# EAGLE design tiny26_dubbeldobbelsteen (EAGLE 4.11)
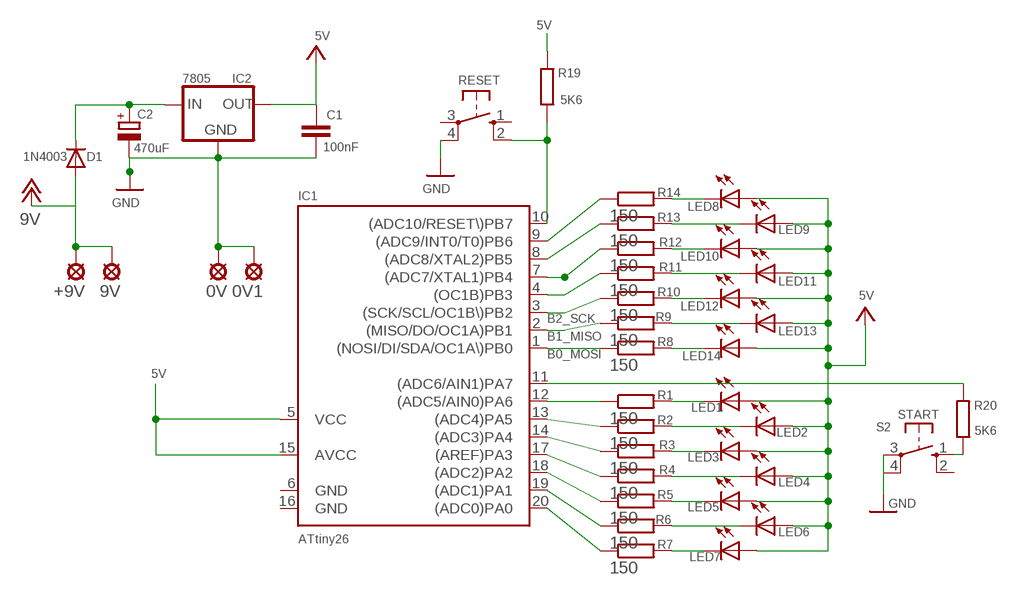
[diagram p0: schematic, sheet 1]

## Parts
0V  SE14  [SE14]
0V1  SE14  [SE14]
9V  SE14  [SE14]
+9V  SE14  [SE14]
C1  100nF  C-EU050-025X075  [C050-025X075]
C2  470uF  CPOL-EUE5-6  [E5-6]
D1  1N4003  DIODE-D-12.5  [D-12.5]
IC1  ATtiny26  TINY26LP  [DIL20]
IC2  7805  78XXS  [78XXS]
LED1  LED3MM  [LED3MM]
LED2  LED3MM  [LED3MM]
LED3  LED3MM  [LED3MM]
LED4  LED3MM  [LED3MM]
LED5  LED3MM  [LED3MM]
LED6  LED3MM  [LED3MM]
LED7  LED3MM  [LED3MM]
LED8  LED3MM  [LED3MM]
LED9  LED3MM  [LED3MM]
LED10  LED3MM  [LED3MM]
LED11  LED3MM  [LED3MM]
LED12  LED3MM  [LED3MM]
LED13  LED3MM  [LED3MM]
LED14  LED3MM  [LED3MM]
R1  150  R-EU_0207/10  [0207/10]
R2  150  R-EU_0207/10  [0207/10]
R3  150  R-EU_0207/10  [0207/10]
R4  150  R-EU_0207/10  [0207/10]
R5  150  R-EU_0207/10  [0207/10]
R6  150  R-EU_0207/10  [0207/10]
R7  150  R-EU_0207/10  [0207/10]
R8  150  R-EU_0207/10  [0207/10]
R9  150  R-EU_0207/10  [0207/10]
R10  150  R-EU_0207/10  [0207/10]
R11  150  R-EU_0207/10  [0207/10]
R12  150  R-EU_0207/10  [0207/10]
R13  150  R-EU_0207/10  [0207/10]
R14  150  R-EU_0207/10  [0207/10]
R19  5K6  R-EU_0207/10  [0207/10]
R20  5K6  R-EU_0207/10  [0207/10]
RESET  10-XX  [B3F-10XX]
S2  START  10-XX  [B3F-10XX]

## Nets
5V: C1.1 IC1.5(VCC) IC1.15(AVCC) IC2.OUT LED1.A LED2.A LED3.A LED4.A LED5.A LED6.A LED7.A LED8.A LED9.A LED10.A LED11.A LED12.A LED13.A LED14.A R19.2
+9V: 9V.MP +9V.MP D1.A ; supply symbol labelled 9V
B0_MOSI: IC1.1((NOSI/DI/SDA/OC1A\)PB0) R8.1
B1_MISO: IC1.2((MISO/DO/OC1A)PB1) R9.1
B2_SCK: IC1.3((SCK/SCL/OC1B\)PB2) R10.1
B3: IC1.4((OC1B)PB3) R11.1
B4: IC1.7((ADC7/XTAL1)PB4) R12.1
GND: 0V1.MP 0V.MP C1.2 C2.- IC2.GND RESET.4(P1) S2.3(P)
N$3: R20.1 S2.1(S)
N$5: LED7.K(C) R7.2
N$6: LED6.K(C) R6.2
N$7: LED5.K(C) R5.2
N$8: LED4.K(C) R4.2
N$9: LED3.K(C) R3.2
N$10: C2.+ D1.C IC2.IN
N$11: LED2.K(C) R2.2
N$12: LED1.K(C) R1.2
N$14: IC1.20((ADC0)PA0) R7.1
N$15: IC1.19((ADC1)PA1) R6.1
N$17: IC1.18((ADC2)PA2) R5.1
N$18: IC1.17((AREF)PA3) R4.1
N$19: IC1.14((ADC3)PA4) R3.1
N$20: IC1.13((ADC4)PA5) R2.1
N$21: IC1.12((ADC5/AIN0)PA6) R1.1
N$23: LED14.K(C) R8.2
N$24: LED13.K(C) R9.2
N$25: LED12.K(C) R10.2
N$26: LED11.K(C) R11.2
N$27: LED10.K(C) R12.2
N$28: LED9.K(C) R13.2
N$29: LED8.K(C) R14.2
N$30: IC1.8((ADC8/XTAL2)PB5) R13.1
N$31: IC1.9((ADC9/INT0/T0)PB6) R14.1
N$62: IC1.11((ADC6/AIN1)PA7) R20.2
RESET: IC1.10((ADC10/RESET\)PB7) R19.1 RESET.2(S1)
Unconnected: RESET.1(S) RESET.3(P) S2.2(S1) S2.4(P1)

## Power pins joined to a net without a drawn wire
GND: IC1.6(GND) IC1.16(GND)

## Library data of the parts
0V 0V1 9V +9V = solpad:SE14: SOLDER PAD
C1 = rcl:C-EU: CAPACITOR, European symbol
C2 = rcl:CPOL-EU: POLARIZED CAPACITOR, European symbol
D1 = diode:DIODE-: DIODE
IC1 = atmel:TINY26*: 8-bit AVR Microcontroller with 2K Bytes Flash
IC2 = v-reg:78XXS: VOLTAGE REGULATOR
LED1-LED14 = led:LED: LED
R1-R14 R19 R20 = rcl:R-EU_: RESISTOR, European symbol
RESET S2 = switch-omron:10-XX: OMRON SWITCH

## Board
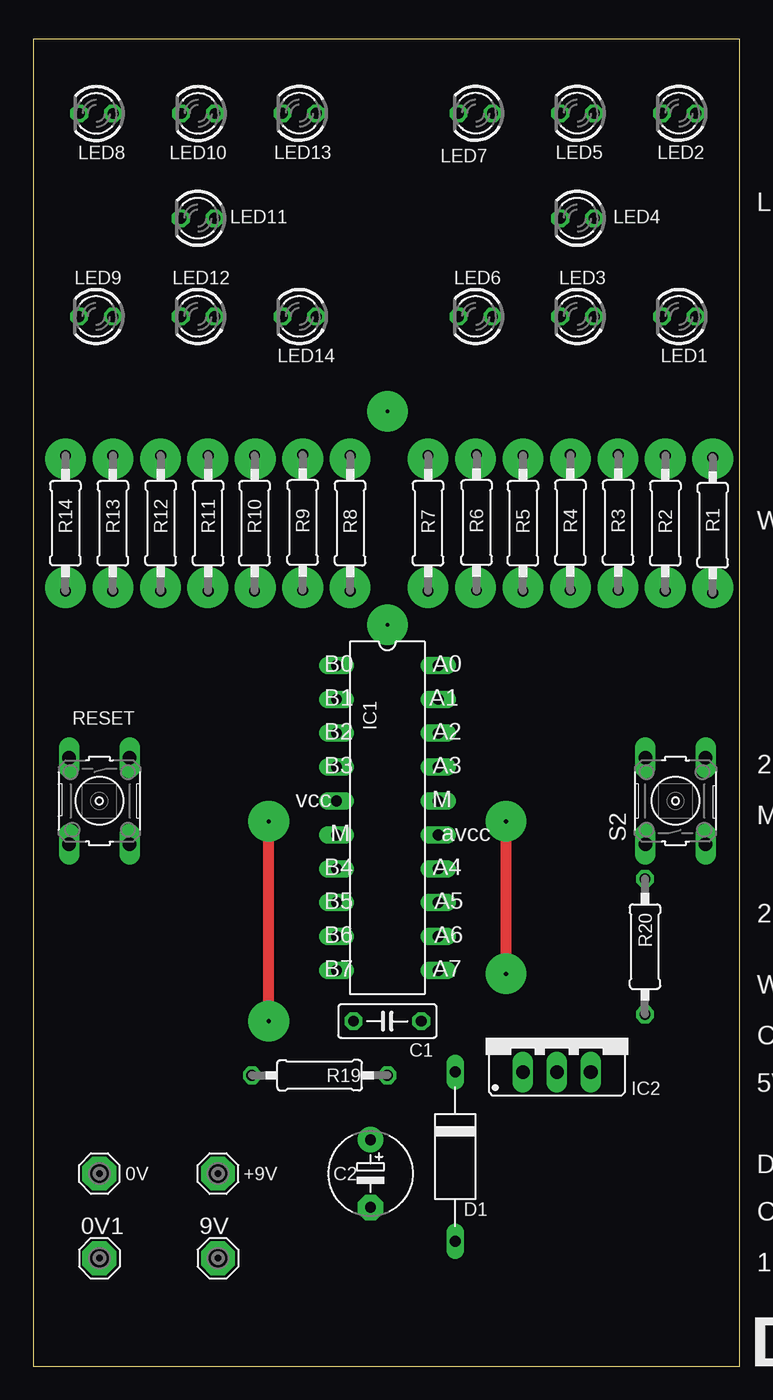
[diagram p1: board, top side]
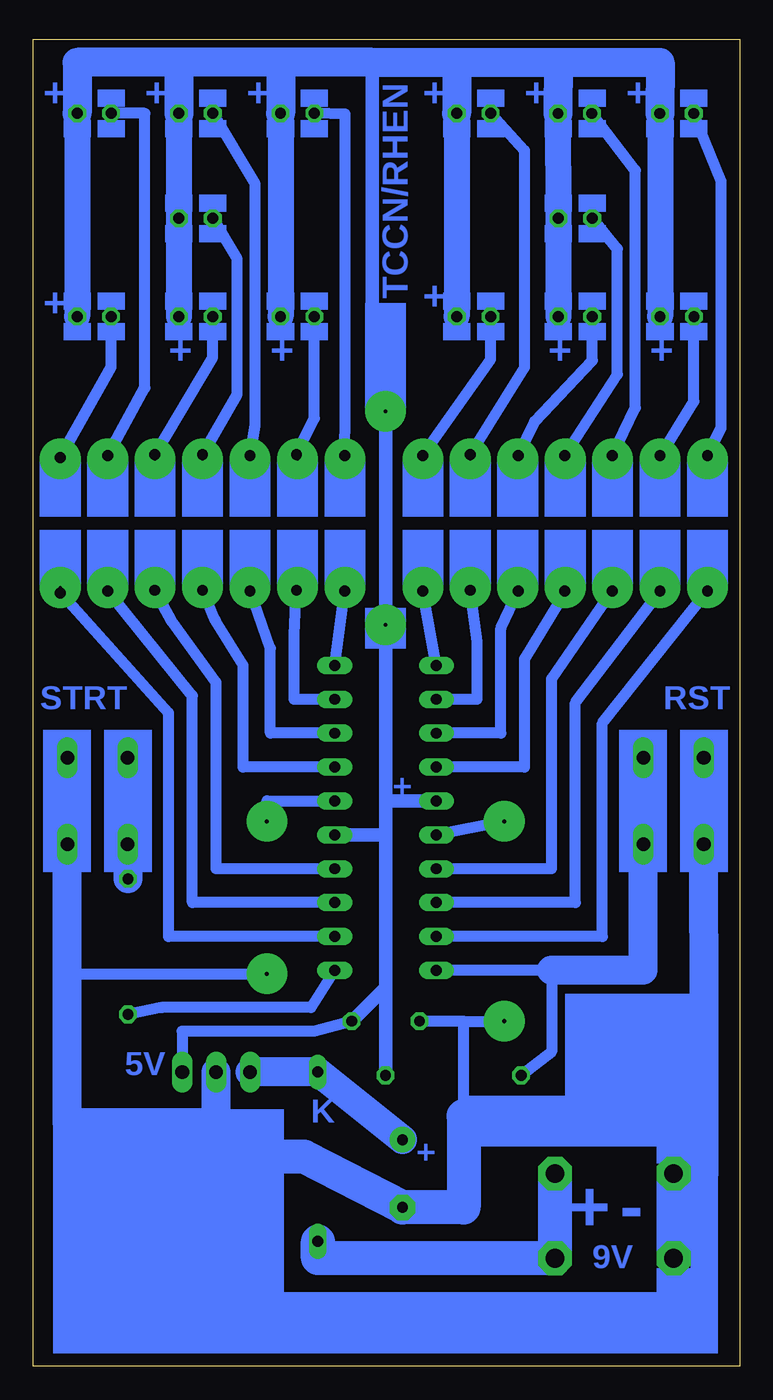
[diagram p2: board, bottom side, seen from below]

Size 52.94 x 99.49 mm. Coordinates in mm from the lower left corner, seen from the top.
Outline: 0,0 52.94,0 52.94,99.49 0,99.49 0,0
Copper layers (1*16): Top 0.035mm / dielectric 1.5mm / Bottom 0.035mm
Design rules "default": minimum track width 24mil, minimum drill 24mil, track to track 15mil, track to pad 15mil, pad to pad 15mil, via to via 15mil, smd to smd 8mil, copper to edge 15mil, drill to drill 8mil, minimum pad ring 10mil, minimum via ring 8mil, stop-mask expansion 4mil, vias tented up to drill 0mil, thermal gap 10mil

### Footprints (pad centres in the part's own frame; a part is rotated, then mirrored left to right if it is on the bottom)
SE14 = drill 1.397 pad 2.54 octagon: MP 0,0
C050-025X075 = drill 0.813 octagon: 1 -2.54,0; 2 2.54,0
E5-6 = drill 0.813 pad 1.905 round: + -2.54,0 | drill 0.813 pad 1.905 octagon: - 2.54,0
D-12.5 = drill 0.813 long: A 6.35,0; C -6.35,0
DIL20 = drill 0.813 long: 1 -11.43,-3.81; 2 -8.89,-3.81; 3 -6.35,-3.81; 4 -3.81,-3.81; 5 -1.27,-3.81; 6 1.27,-3.81; 7 3.81,-3.81; 8 6.35,-3.81; 9 8.89,-3.81; 10 11.43,-3.81; 11 11.43,3.81; 12 8.89,3.81; 13 6.35,3.81; 14 3.81,3.81; 15 1.27,3.81; 16 -1.27,3.81; 17 -3.81,3.81; 18 -6.35,3.81; 19 -8.89,3.81; 20 -11.43,3.81
78XXS = drill 1.016 long: GND 0,-2.54; IN -2.54,-2.54; OUT 2.54,-2.54
LED3MM = drill 0.813 octagon: A -1.27,0; K 1.27,0
0207/10 = drill 0.813 octagon: 1 -5.08,0; 2 5.08,0
B3F-10XX = drill 1.016 long: 1 -3.251,2.261; 2 3.251,2.261; 3 -3.251,-2.261; 4 3.251,-2.261

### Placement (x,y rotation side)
0V  4.95,14.44 180 top
0V1  4.95,8.09 0 top
9V  13.84,8.09 0 top
+9V  13.84,14.44 180 top
C1  26.54,25.87 180 top
C2  25.27,14.44 270 top
D1  31.62,15.71 270 top
IC1  26.54,41.11 270 top
IC2  39.24,24.6 0 top
LED1  48.38,78.7 180 top
LED2  48.38,93.94 180 top
LED3  40.76,78.7 180 top
LED4  40.76,86.07 180 top
LED5  40.76,93.94 180 top
LED6  33.14,78.7 180 top
LED7  33.14,93.94 180 top
LED8  4.71,93.93 180 top
LED9  4.69,78.7 180 top
LED10  12.35,93.93 180 top
LED11  12.31,86.07 180 top
LED12  12.31,78.7 180 top
LED13  19.93,93.94 180 top
LED14  19.93,78.7 180 top
R1  50.92,63.06 90 top
R2  47.37,63.21 90 top
R3  43.84,63.26 90 top
R4  40.25,63.26 90 top
R5  36.7,63.21 90 top
R6  33.22,63.26 90 top
R7  29.59,63.21 90 top
R8  23.74,63.21 90 top
R9  20.19,63.26 90 top
R10  16.58,63.21 90 top
R11  13.1,63.21 90 top
R12  9.55,63.21 90 top
R13  5.96,63.21 90 top
R14  2.41,63.21 90 top
R19  21.46,21.81 0 top
R20  45.84,31.46 270 top
RESET  4.95,42.38 270 top
S2  48.13,42.38 90 top

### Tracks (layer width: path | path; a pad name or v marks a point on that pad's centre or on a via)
5V
  Bottom 0.813: IC2.OUT 41.78,25.11 31.87,25.11 C1.1
  Bottom 1.016: 26.54,42.38 IC1.5 | 26.54,42.38 26.54,75.65 27.55,75.65 27.55,97.75 | 26.54,28.41 26.54,39.84 | 26.54,39.84 26.54,42.38 | 26.54,28.41 C1.1 | 26.54,39.84 IC1.15 | R19.2 26.54,28.41 | LED8.A 5.96,93.94
  Bottom 1.93: LED2.A LED1.A | LED13.A LED14.A | LED7.A LED6.A | LED3.A LED4.A LED5.A | LED12.A LED11.A LED10.A | 5.96,93.94 LED9.A
  Bottom 2.184: 13.58,97.75 5.96,97.75 LED8.A | 21.2,97.75 LED13.A | 21.2,97.75 13.58,97.75 | 21.2,97.75 27.55,97.75 34.41,97.75 | 34.41,97.75 42.03,97.75 | LED2.A 49.65,97.75 42.03,97.75 | 34.41,97.75 LED7.A | 42.03,97.75 LED5.A | 13.58,97.75 LED10.A
+9V
  Bottom 2.54: +9V.MP 9V.MP 31.62,8.09 D1.A
B0_MOSI
  Bottom 0.813: IC1.1 R8.1
B1_MISO
  Bottom 0.813: IC1.2 19.68,50 19.68,54.32 R9.1
B2_SCK
  Bottom 0.813: IC1.3 17.9,47.46 17.9,55.33 R10.1
B3
  Bottom 0.813: IC1.4 16.12,44.92 16.12,53.05 12.92,58.31 R11.1
B4
  Bottom 0.813: IC1.7 14.09,37.3 14.09,51.52 R12.1
GND  (via drill 0.3 pad 3.05)
  Top 0.813: v35.43,29.43 v35.43,40.86 | v17.65,25.87 v17.65,40.86
  Bottom 0.406: 2.66,18.76 20.7,18.76
  Bottom 0.813: v35.43,40.86 35.43,42.38 IC1.16 | v17.65,40.86 IC1.6 | 50.41,29.43 v35.43,29.43 | 20.7,25.87 v17.65,25.87 | 20.7,18.76 20.7,25.87 | 20.7,25.87 C1.2 | 35.43,15.71 35.43,18.25 39.24,18.25
  Bottom 1.422: 50.41,30.44 50.67,30.44
  Bottom 2.184: S2.3 50.41,30.44 50.41,29.43 50.41,18.25 39.24,18.25 IC2.GND | RESET.4 2.66,25.79 2.66,18.76 2.66,14.44 0V.MP
  Bottom 2.54: 35.43,15.71 32.63,15.71 C2.- 20.7,11.9 20.7,18.76 | 0V1.MP 0V.MP
N$2  (via drill 0.25 pad 3.05)
  other vias: 2.41,68.03
N$3
  Bottom 0.813: 45.84,39.08 S2.1
  Bottom 2.184: R20.1 45.84,39.08
N$5
  Bottom 0.813: LED7.K 29.56,93.89 29.56,71.54 R7.2
N$6
  Bottom 0.813: R6.2 31.87,71.08 LED6.K
N$7
  Bottom 0.813: LED5.K 36.32,88.63 36.32,70.57 R5.2
N$8
  Bottom 0.813: LED4.K 37.66,83.02 37.66,72.86 R4.2
N$9
  Bottom 0.813: LED3.K 39.49,75.65 R3.2
N$10
  Bottom 2.184: C2.+ D1.C IC2.IN
N$11
  Bottom 0.813: LED2.K 44.57,93.94 44.57,73.37 R2.2
N$12
  Bottom 0.813: R1.2 47.11,74.89 LED1.K
N$14
  Bottom 0.813: IC1.20 R7.1
N$15
  Bottom 0.813: IC1.19 33.4,50 33.4,54.83 R6.1
N$17
  Bottom 0.813: IC1.18 35.17,47.46 35.17,53.81 R5.1
N$18
  Bottom 0.813: IC1.17 37.21,44.92 37.21,52.54 39.29,55.92 R4.1
N$19
  Bottom 0.813: IC1.14 39.24,37.3 39.24,51.27 42.57,55.87 R3.1
N$20
  Bottom 0.813: IC1.13 41.02,34.76 41.02,50.25 R2.1
N$21
  Bottom 0.813: IC1.12 42.79,32.22 42.79,48.98 50.92,58.05 R1.1
N$22  (via drill 0.25 pad 3.05)
  other vias: 5.96,68.03
N$23
  Bottom 0.813: LED14.K 18.66,75.48 R8.2
N$24
  Bottom 0.813: LED13.K 16.12,91.15 16.12,74.89 R9.2
N$25
  Bottom 0.813: R10.2 15.36,70.83 11.04,75.4 LED12.K
N$26
  Bottom 0.813: R11.2 9.16,74.36 9.16,83.76 LED11.K
N$27
  Bottom 0.813: LED10.K 7.82,89.65 7.82,71.87 R12.2
N$28
  Bottom 0.813: LED9.K 3.42,72.35 R13.2
N$29
  Bottom 0.813: LED8.K 1.39,88.86 1.39,70.32 R14.2
N$30
  Bottom 0.813: IC1.8 12.31,34.76 12.31,49.75 R13.1
N$31
  Bottom 0.813: IC1.9 10.28,32.22 10.28,48.22 R14.1
N$32  (via drill 0.25 pad 3.05)
  other vias: 9.52,68.03
N$33  (via drill 0.25 pad 3.05)
  other vias: 13.08,68.03
N$34  (via drill 0.25 pad 3.05)
  other vias: 2.41,58.38
N$35  (via drill 0.25 pad 3.05)
  other vias: 5.96,58.38
N$36  (via drill 0.25 pad 3.05)
  other vias: 9.52,58.38
N$37  (via drill 0.25 pad 3.05)
  other vias: 13.08,58.38
N$38  (via drill 0.25 pad 3.05)
  other vias: 16.63,68.03
N$39  (via drill 0.25 pad 3.05)
  other vias: 20.19,68.03
N$40  (via drill 0.25 pad 3.05)
  other vias: 23.74,68.03
N$41  (via drill 0.25 pad 3.05)
  other vias: 29.59,68.03
N$42  (via drill 0.25 pad 3.05)
  other vias: 33.14,68.03
N$43  (via drill 0.25 pad 3.05)
  other vias: 29.59,58.38
N$44  (via drill 0.25 pad 3.05)
  other vias: 23.74,58.38
N$45  (via drill 0.25 pad 3.05)
  other vias: 20.19,58.38
N$46  (via drill 0.25 pad 3.05)
  other vias: 16.63,58.38
N$47  (via drill 0.25 pad 3.05)
  other vias: 33.14,58.38
N$48  (via drill 0.25 pad 3.05)
  other vias: 36.7,68.03
N$49  (via drill 0.25 pad 3.05)
  other vias: 36.7,58.38
N$50  (via drill 0.25 pad 3.05)
  other vias: 40.25,68.03
N$51  (via drill 0.25 pad 3.05)
  other vias: 40.25,58.38
N$52  (via drill 0.25 pad 3.05)
  other vias: 43.81,68.03
N$53  (via drill 0.25 pad 3.05)
  other vias: 43.81,58.38
N$54  (via drill 0.25 pad 3.05)
  other vias: 47.37,68.03
N$55  (via drill 0.25 pad 3.05)
  other vias: 47.37,58.38
N$56  (via drill 0.25 pad 3.05)
  other vias: 50.92,68.03
N$57  (via drill 0.25 pad 3.05)
  other vias: 50.92,58.38
N$58  (via drill 0.25 pad 3.05)
  other vias: 26.54,71.59
N$59  (via drill 0.25 pad 3.05)
  other vias: 26.54,55.59
N$62
  Bottom 0.813: IC1.11 32.13,26.89 43.3,26.89 R20.2
RESET
  Bottom 0.813: IC1.10 14.09,29.68 14.09,23.58 R19.1
  Bottom 2.184: RESET.2 7.23,29.68 14.09,29.68
(copper drawn outside any net)
  shapes: Bottom area x100

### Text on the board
Bottom: TCCN/RHEN | + | + | + | + | + | + | + | + | + | + | + | + | RST | STRT | + | 5V | K | + | - | + | 9V
tNames: LED | LED1 t+m LED14, platte kant (-) links. | Platte kant. | (-) Kathode | Anode (+) | Langer pootje | Weerstanden R1 t+m R14, 150 ohm (bruin/groen/zwart/zwart/bruin) | B0 | A0 | B1 | A1 | B2 | A2 | B3 | A3 | 2 Drukknopjes | vcc | M | M | avcc | Microcontroller IC1 ATTINY26 + voetje, inkeping richting | B4 | A4 | B5 | A5 | B6 | A6 | 2 Draadbruggen. | B7 | A7 | Weerstanden R19, R20, 5600 ohm (groen/blauw/rood/goud) | Condensator C1 100 nF | 5V Spanningsregelaar IC2 7805, metaalkant richting | Diode D1, kathode (=- witte streep) richting | Condensator C2, 470 uF, witte streep (-) richting | 1 Batterij clip voor 9V blokbatterij, rode draad rechts (+) | Dubbele Dobbelsteen | TCCNijmegen.nl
